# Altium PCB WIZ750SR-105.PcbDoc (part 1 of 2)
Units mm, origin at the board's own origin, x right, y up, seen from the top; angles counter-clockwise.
Board outline 62 x 40 mm, 4 copper layers (Top Layer, Signal Layer 1, Internal Plane 1, Bottom Layer), stack 0.844 mm thick; 87 components, 85 nets, 410 pads, 285 vias.
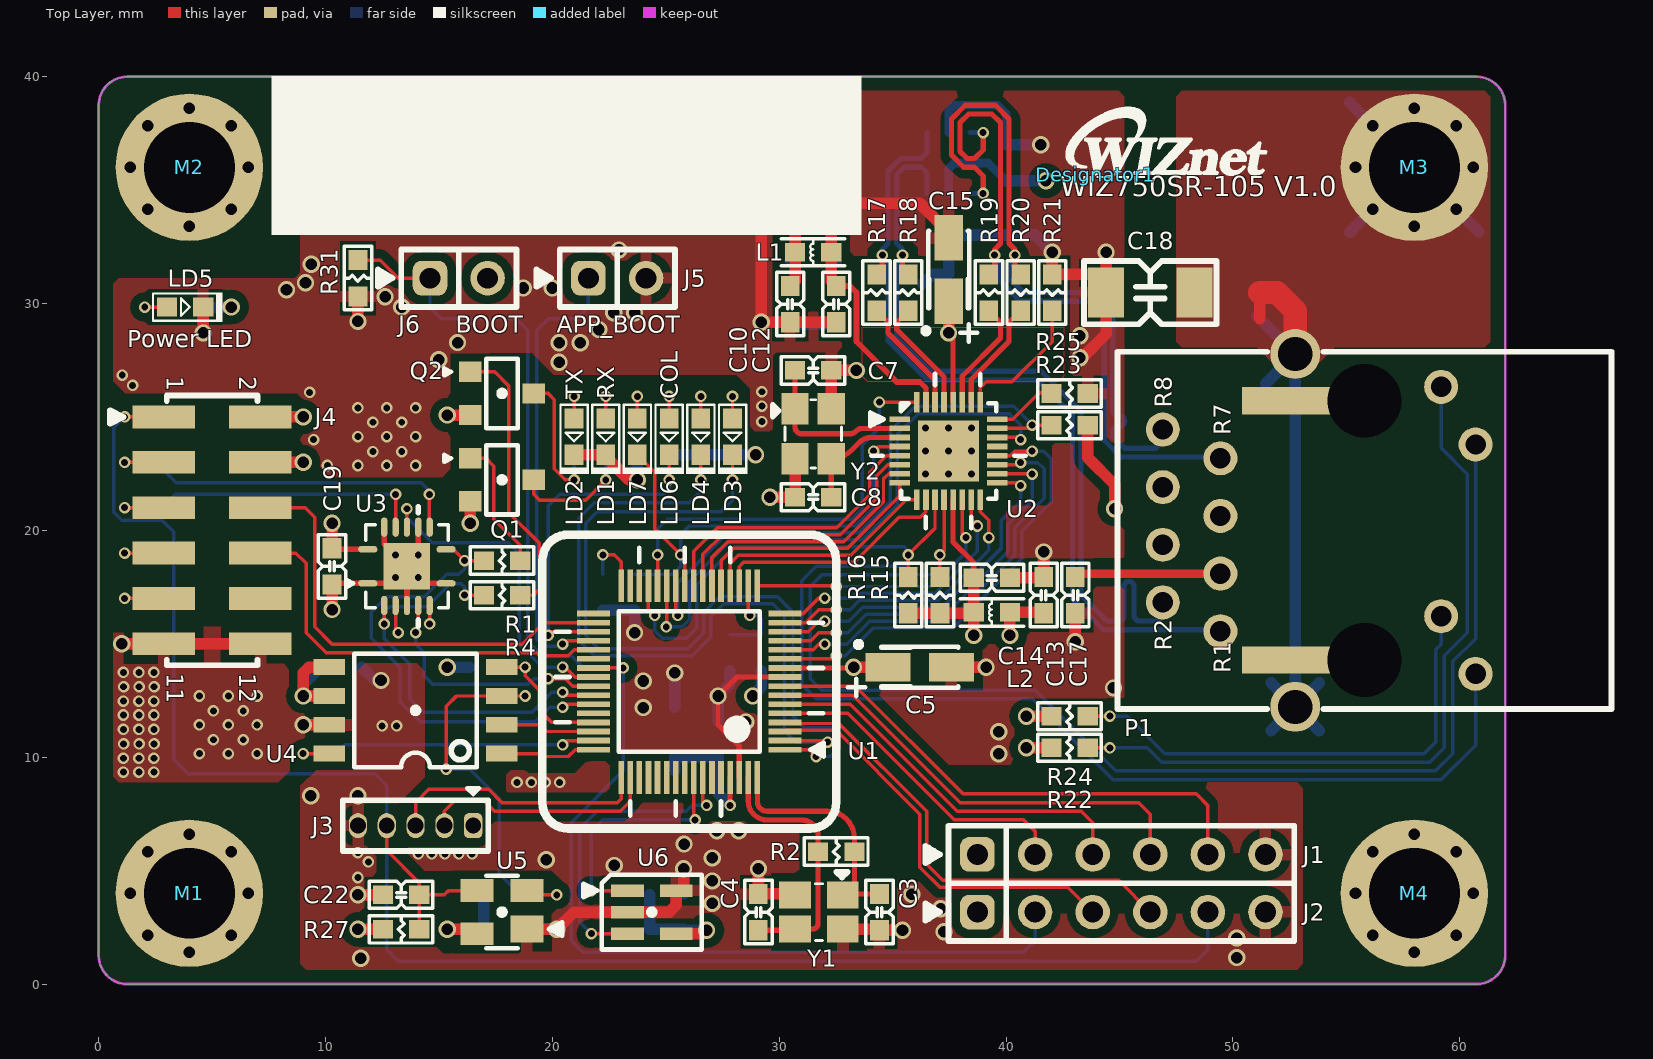
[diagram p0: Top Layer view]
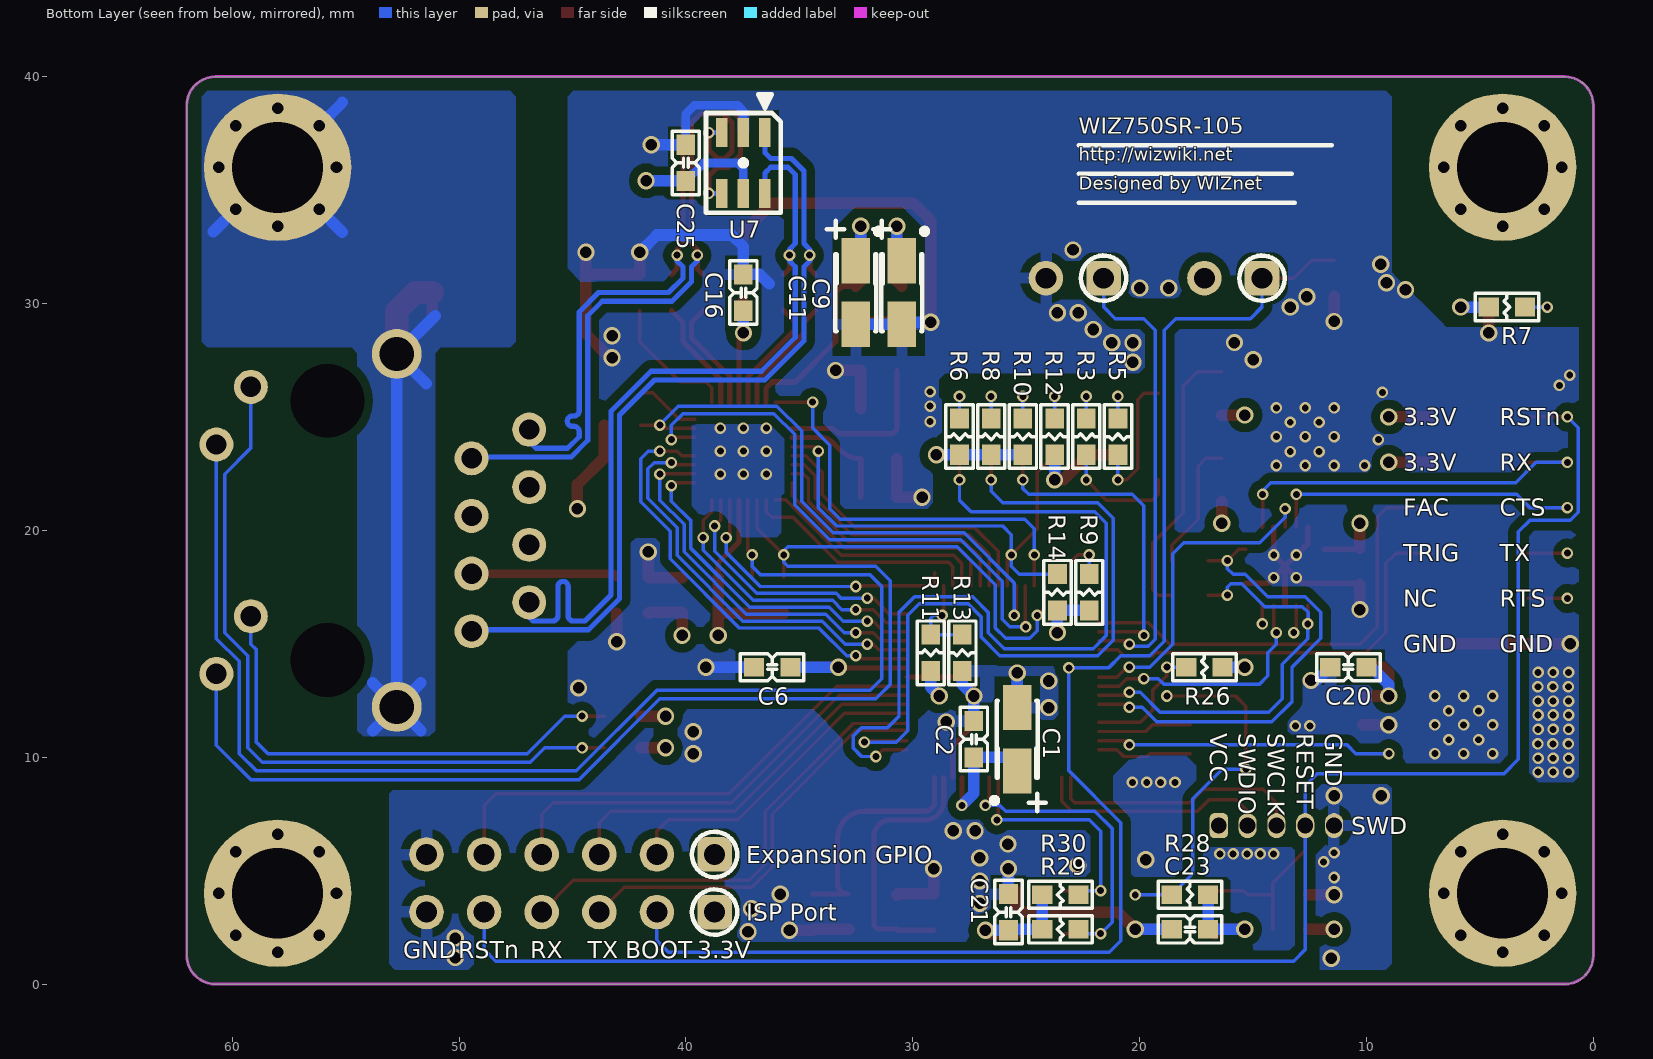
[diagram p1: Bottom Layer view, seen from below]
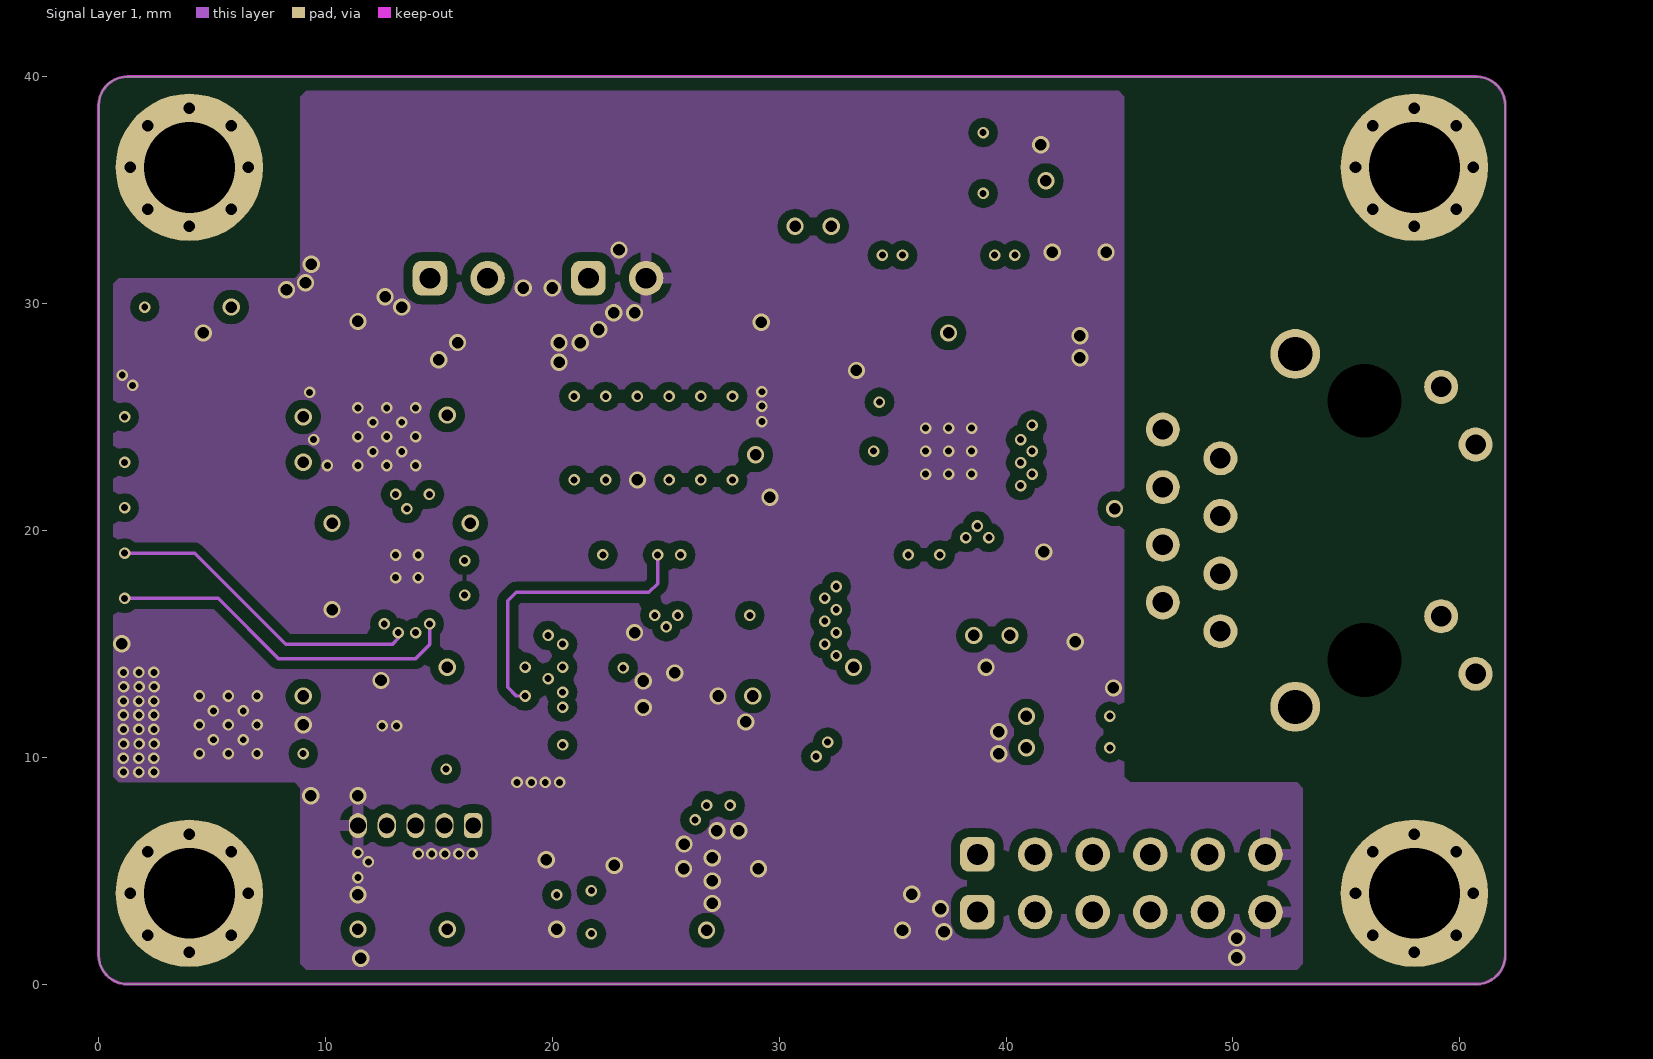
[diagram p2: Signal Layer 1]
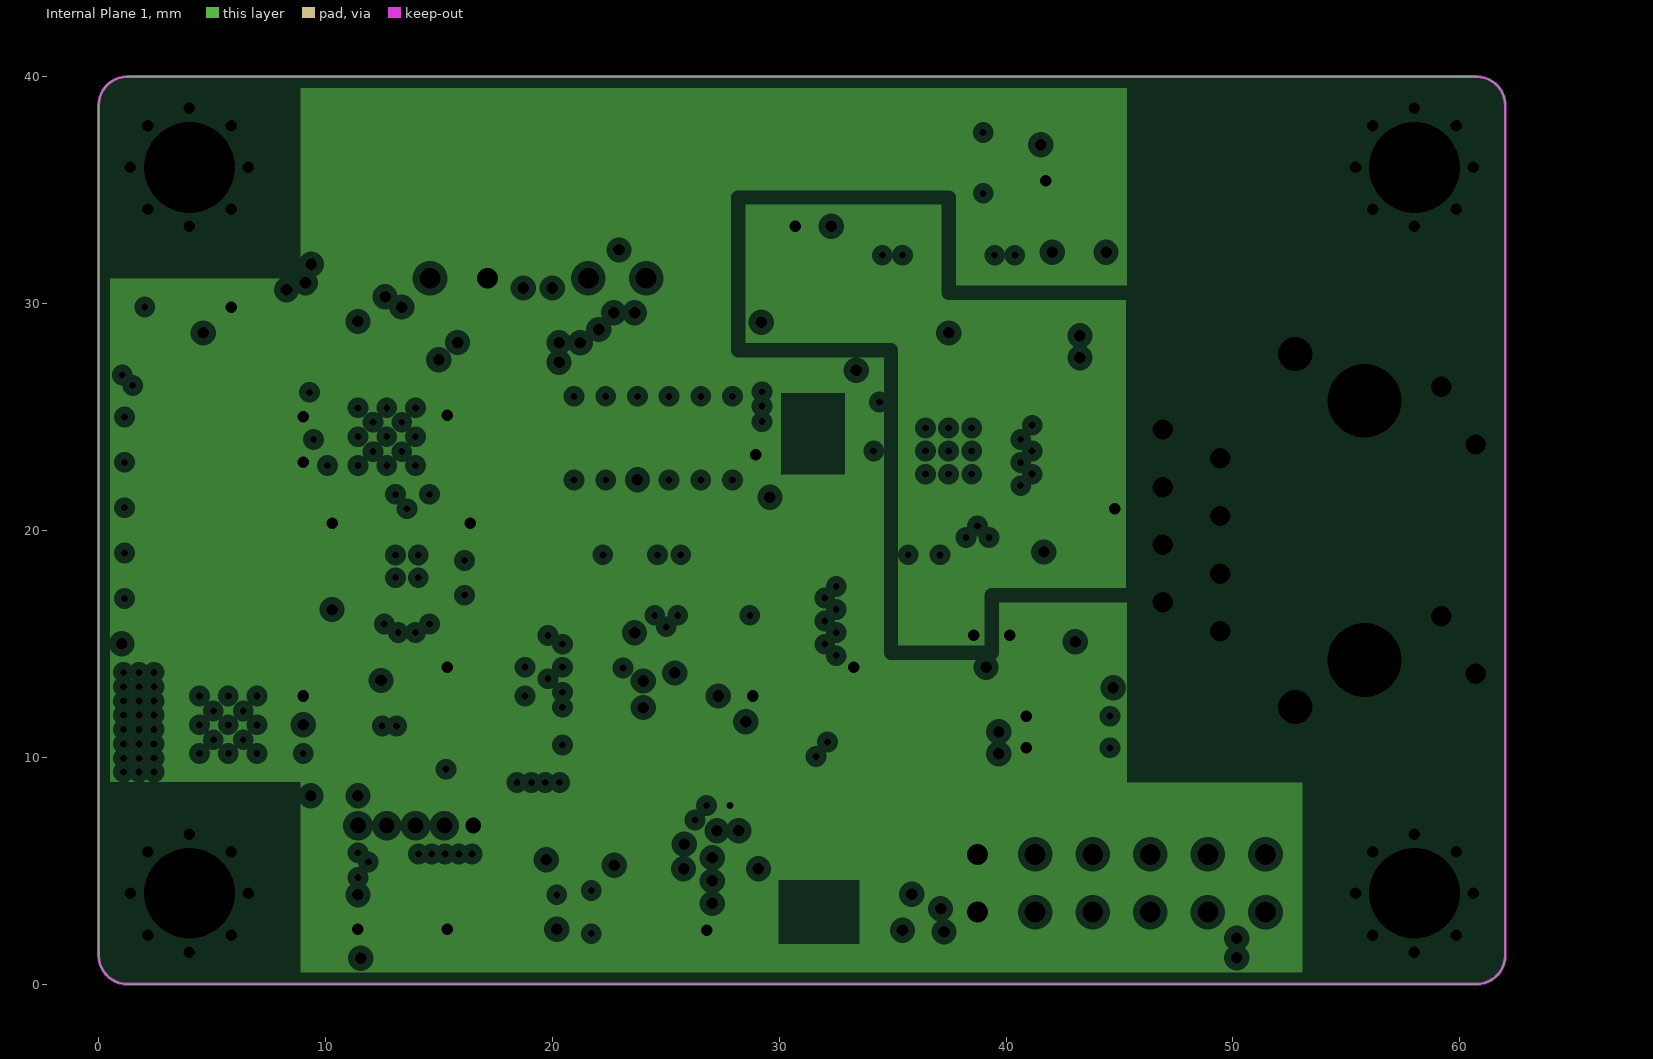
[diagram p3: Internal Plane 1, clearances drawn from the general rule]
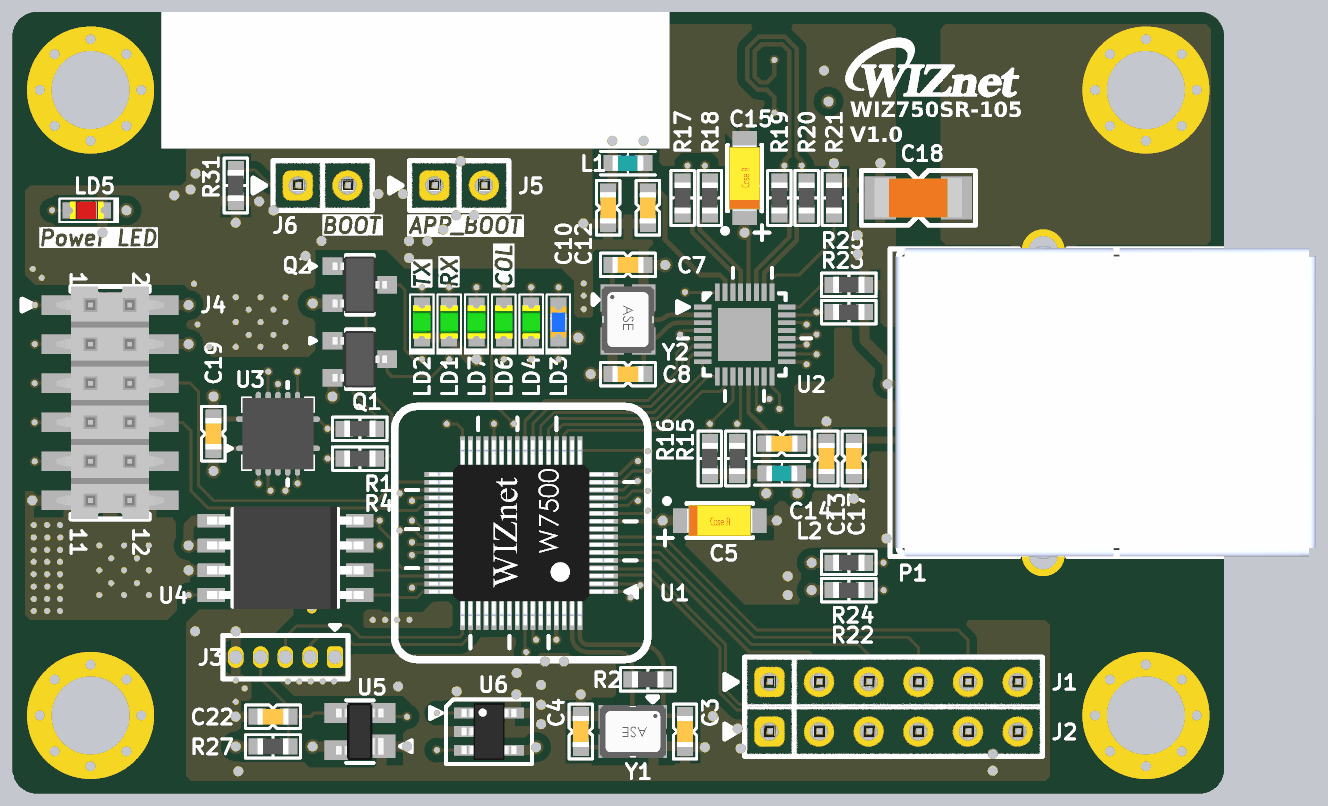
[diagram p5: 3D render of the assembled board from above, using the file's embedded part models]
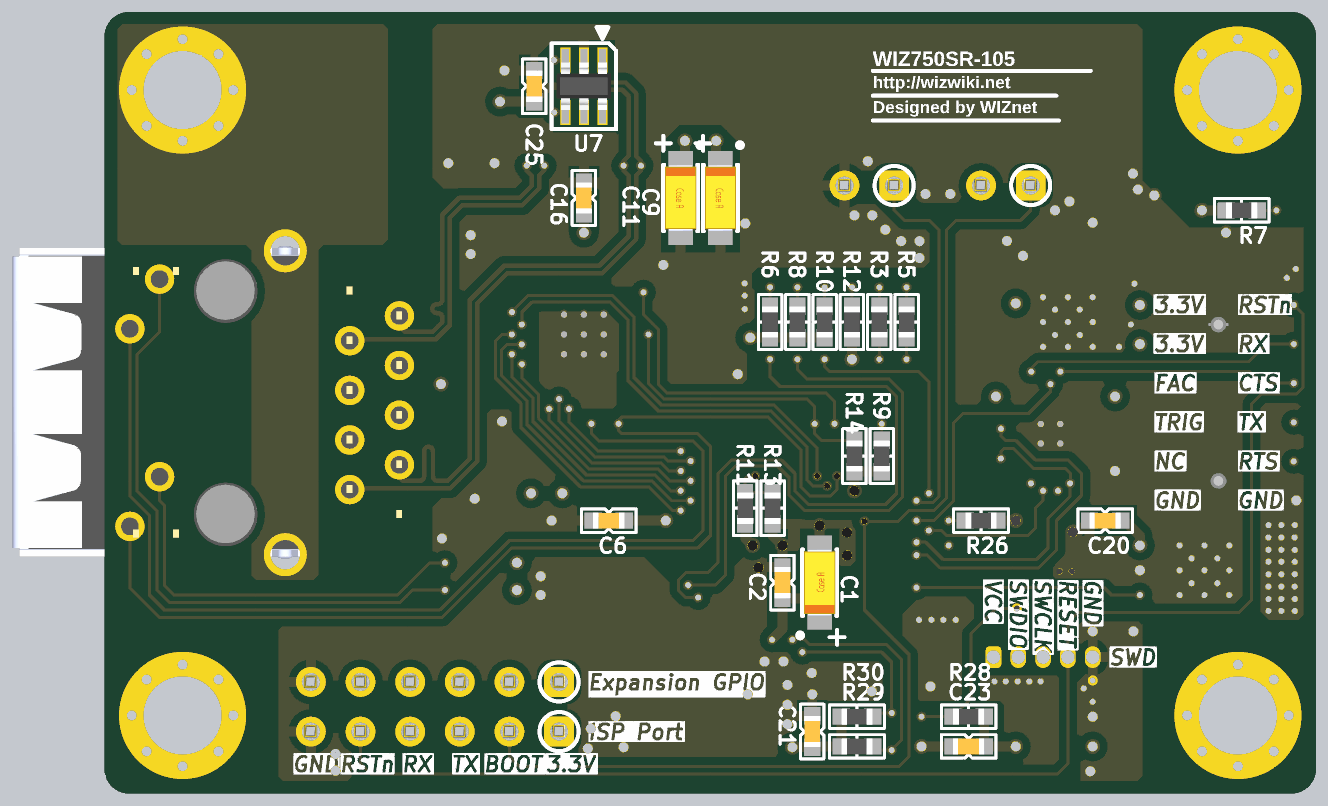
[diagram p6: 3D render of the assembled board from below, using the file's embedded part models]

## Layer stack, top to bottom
Top Solder: solder mask 0.0102, Solder Resist, Dk 3.5
Top Layer: signal copper 0.0356
Dielectric1: core 0.32, FR-4, Dk 4.8
Signal Layer 1: signal copper 0.036
Dielectric 6: prepreg 0.127, Dk 4.2
Internal Plane 1: plane copper 0.0356, net (Multiple Nets)
Dielectric5: core 0.254, FR-4, Dk 4.2
Bottom Layer: signal copper 0.0356
Bottom Solder: solder mask 0.0102, Solder Resist, Dk 3.5

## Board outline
0,1.27 0,38.73 cw(c1.27,38.73) 1.27,40 60.73,40 cw(c60.73,38.73) 62,38.73 62,1.27 cw(c60.73,1.27) 60.73,0 1.27,0 cw(c1.27,1.27)

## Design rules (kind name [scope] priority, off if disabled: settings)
Clearance [All] p1: gap=0.15 except(0.381: Arc-Poly Track-Poly SMDPad-Poly THPad-Poly Via-Poly Fill-Poly Poly-Poly Poly-Region)
DiffPairsRouting [All] p1: maxlimit=0.152 minlimit=0.152 mostfreqgap=0.152 toplayer_minwidth=0.152 toplayer_maxwidth=0.229 toplayer_prefwidth=0.229 midlayer1_minwidth=0.152 midlayer1_maxwidth=0.229 midlayer1_prefwidth=0.229 bottomlayer_minwidth=0.152 bottomlayer_maxwidth=0.229 bottomlayer_prefwidth=0.229 maxuncoupledlength=15.24
HoleSize [All] p1: absolutevalues=TRUE maxlimit=4.064 minlimit=0.025 maxpercent=80.000 minpercent=20.000
PlaneClearance [All] p1: clearance=0.305
PlaneConnect [All] p1: planeconnectstyle=Direct reliefexpansion=0.508 reliefentries=4 reliefconductorwidth=0.254 reliefairgap=0.254
PolygonConnect PolygonConnect_2 [IsPad vs IsNamedPolygon('Top Layer-GND') Or  IsNamedPolygon('Bottom Layer-GND')] p1: connectstyle=Relief reliefconductorwidth=0.508 reliefentries=4 polygonreliefangle="90 Angle" airgapwidth=0.381
PolygonConnect PolygonConnect_1 [IsVia] p2: connectstyle=Direct reliefconductorwidth=0.254 reliefentries=4 polygonreliefangle="90 Angle" airgapwidth=0.254
PolygonConnect [All] p3: connectstyle=Direct reliefconductorwidth=0.254 reliefentries=4 polygonreliefangle="90 Angle" airgapwidth=0.254
RoutingVias [All] p1: holewidth=0.305 width=0.508 viastyle="Through Hole" minholewidth=0.305 minwidth=0.508 maxholewidth=0.508 maxwidth=0.762
SolderMaskExpansion [All] p1: expansion=0
Width [All] p1: maxlimit=2.54 minlimit=0.102 preferedwidth=0.152
26 further rules are at their usual default settings.

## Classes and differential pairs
component class 1.WIZ750JR_W7500: LD2
differential pair MDI0_R: +MDI0_R_P -MDI0_R_N
differential pair MDI0_T: +MDI0_T_P -MDI0_T_N
differential pair MDI_R: +MDI_R_P -MDI_R_N
differential pair MDI_T: +MDI_T_P -MDI_T_N
differential pair NewDifferentialPair1: +U_TXD2 -U_RXD2
differential pair NewDifferentialPair2: +U_TXD0 -U_RXD0

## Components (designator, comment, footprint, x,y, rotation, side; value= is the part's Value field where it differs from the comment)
C1 "10uF/16V" "CAP-A Size" 25.4,10.795 r90 bottom
C2 "1uF" CAP-0603 27.305,10.795 r270 bottom
C3 "30pF" CAP-0603 34.417,3.175 r90 top
C4 "30pF" CAP-0603 29.083,3.175 r270 top
C5 "10uF/16V" "CAP-A Size" 36.195,13.97 r0 top
C6 "1uF" CAP-0603 36.195,13.97 r180 bottom
C7 "27pF" CAP-0603 31.496,27.051 r180 top
C8 "27pF" CAP-0603 31.496,21.463 r0 top
C9 "10uF/16V" "CAP-A Size" 30.48,30.48 r270 bottom
C10 "0.1uF" CAP-0603 30.48,29.972 r90 top
C11 "10uF/16V" "CAP-A Size" 32.512,30.48 r270 bottom
C12 "0.1uF" CAP-0603 32.512,29.972 r90 top
C13 "0.1uF" CAP-0603 41.656,17.145 r270 top
C14 "0.1uF" CAP-0603 39.37,17.907 r0 top
C15 "10uF/16V" "CAP-A Size" 37.465,31.496 r90 top
C16 "0.1uF" CAP-0603 37.465,30.48 r270 bottom
C17 "0.1uF" CAP-0603 43.053,17.145 r90 top
C18 "1nF/2kV" CAP-1808 46.355,30.48 r0 top
C19 "0.1uF" CAP-0603 10.287,18.415 r270 top
C20 "0.1uF(NM)" CAP-0603 10.795,13.97 r0 bottom
C21 "0.1uF(NM)" CAP-0603 25.781,3.175 r270 bottom
C22 "0.1uF" CAP-0603 13.335,3.937 r0 top
C23 "0.1uF" CAP-0603 17.78,2.413 r180 bottom
C25 "0.1uF" CAP-0603 40.005,36.195 r90 bottom
Designator1 "Comment" LOGO-WIZNET(SMALL) 43.942,35.687 r0 top locked
J1 "2.54mm 1x6 Pin Header DIP" IDC-1X6 38.735,5.715 r0 top
J2 "2.54mm 1x6 Pin Header DIP(NM)" IDC-1X6 38.735,3.175 r0 top
J3 "1.27mm_1x5_Pin_header_DIP(NM)" IDC-1X5(1.27MM) 16.51,6.985 r180 top
J4 "2.00mm 6x2 Pin Header SMD" MOLEX-SD-87759-12 5,20 r270 top locked
J5 "2.54mm 1x2 Pin Header DIP" IDC-1X2 21.59,31.115 r0 top
J6 "2.54mm 1x2 Pin Header DIP" IDC-1X2 14.605,31.115 r0 top
L1 "HH-1M1608-121JT" IND-0603 31.496,32.258 r180 top
L2 "HH-1M1608-121JT" IND-0603 39.37,16.383 r180 top
LD1 "GREEN-0603" LED-0603-GREEN 22.352,24.13 r270 top
LD2 "GREEN-0603" LED-0603-GREEN 20.955,24.13 r270 top
LD3 "BLUE-0603" LED-0603-BLUE 27.94,24.13 r270 top
LD4 "GREEN-0603" LED-0603-GREEN 26.543,24.13 r270 top
LD5 "RED-0603" LED-0603-RED 3.81,29.845 r0 top
LD6 "GREEN-0603" LED-0603-GREEN 25.146,24.13 r270 top
LD7 "GREEN-0603" LED-0603-GREEN 23.749,24.13 r270 top
M1 "Comment" HOLE-4/6.5 4,4 r0 top locked
M2 "Comment" HOLE-4/6.5 4,36 r0 top locked
M3 "Comment" HOLE-4/6.5 58,36 r0 top locked
M4 "Comment" HOLE-4/6.5 58,4 r0 top locked
P1 "BS-RB10005" RJ45-RB10005 55.795,20 r90 top locked
Q1 "Q-MMBT4403" SOT-23-3L 17.78,22.225 r270 top
Q2 "Q-MMBT4403" SOT-23-3L 17.78,26.035 r270 top
R1 "1K" RES-0603 17.78,18.669 r180 top
R2 "1M" RES-0603 32.512,5.842 r180 top
R3 "330R" RES-0603 22.352,24.13 r270 bottom
R4 "1K" RES-0603 17.78,17.145 r180 top
R5 "330R" RES-0603 20.955,24.13 r90 bottom
R6 "1K" RES-0603 27.94,24.13 r270 bottom
R7 "330R" RES-0603 3.81,29.845 r180 bottom
R8 "330R" RES-0603 26.543,24.13 r270 bottom
R9 "4.7K" RES-0603 22.225,17.272 r90 bottom
R10 "330R" RES-0603 25.146,24.13 r270 bottom
R11 "4.7K/NC" RES-0603 29.21,14.605 r270 bottom
R12 "330R" RES-0603 23.749,24.13 r270 bottom
R13 "4.7K" RES-0603 27.813,14.605 r90 bottom
R14 "5.1K" RES-0603 23.622,17.272 r90 bottom
R15 "5.1K" RES-0603 37.084,17.145 r90 top
R16 "5.1K" RES-0603 35.687,17.145 r90 top
R17 "3.3R" RES-0603 34.29,30.48 r270 top
R18 "3.3R" RES-0603 35.687,30.48 r270 top
R19 "3.3R" RES-0603 39.243,30.48 r270 top
R20 "3.3R" RES-0603 40.64,30.48 r270 top
R21 "6.19K / 1%" RES-0603 42.037,30.48 r270 top
R22 "330R" RES-0603 42.799,10.414 r0 top
R23 "5.1K" RES-0603 42.799,24.638 r0 top
R24 "330R" RES-0603 42.799,11.811 r0 top
R25 "5.1K" RES-0603 42.799,26.035 r180 top
R26 "4.7K(NM)" RES-0603 17.145,13.97 r180 bottom
R27 "4.7K" RES-0603 13.335,2.413 r180 top
R28 "4.7K" RES-0603 17.78,3.937 r180 bottom
R29 "4.7K(NM)" RES-0603 23.495,2.413 r0 bottom
R30 "4.7K(NM)" RES-0603 23.495,3.937 r0 bottom
R31 "4.7K" RES-0603 11.43,31.115 r270 top
U1 "W7500" W7500-LQFP64 26.035,13.335 r180 top locked
U2 "IP101GR/GRI" QFN32(0.4/4X4) 37.465,23.495 r0 top locked
U3 "SN74LVC125A" VQFN14(0.5/3.65X3.65) 13.589,18.415 r0 top locked
U4 "AT45DB161E-SHF-T" SO-08-EIAJ 13.97,12.065 r180 top
U5 "MIC811SUY" SOT-143 17.78,3.175 r90 top
U6 "24AA16T-I/OT" SOT-23-5L 24.384,3.175 r0 top locked
U7 "TPD4S009" SOT-23-6L 37.465,36.195 r270 bottom
Y1 "12MHz" OSC-TZ1067B 31.75,3.175 r180 top
Y2 "25MHz" OSC-82J0626 31.496,24.257 r270 top

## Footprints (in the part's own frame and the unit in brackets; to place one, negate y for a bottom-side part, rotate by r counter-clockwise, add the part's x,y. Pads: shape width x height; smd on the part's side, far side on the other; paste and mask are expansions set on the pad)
CAP-0603 [mm] "Ceramic CAP 0603(1608)"
  rect 0.89x0.82 smd: 1(-0.8,0) 2(0.8,0)
  silkscreen extent -1.4,-0.6 1.4,0.6, body extent -0.93,-0.41 0.93,0.41, height 0.81
CAP-1808 [mm] "Ceramic CAP 1808(4520)"
  rect 1.6x2.2 smd: 1(-1.95,0) 2(1.95,0)
  silkscreen extent -2.92,-1.4 2.92,1.4, body extent -2.25,-1.02 2.25,1.01, height 2
"CAP-A Size" [mm] "Tantal CAP A Size EIA/IECQ 3216"
  rect 2x1.25 smd: 1(-1.4,0) 2(1.4,0)
  silkscreen extent -3.17,-1.27 1.7,1.12, body extent -1.7,-0.8 1.7,0.8, height 1.75
HOLE-4/6.5 [mm]
  round 6.5 hole 4: 1(0,0)
IDC-1X2 [mil]
  rrect50% 60x60 hole 36: 1(0,0)
  round 60 hole 36: 2(100,0)
  silkscreen extent -90,-50 150,50, body extent -49,-49 151,51, height 336
IDC-1X5(1.27MM) [mm]
  rrect50% 0.8x1.1 hole 0.7: 1(0,0)
  oval 0.8x1.1 hole 0.7: 2(1.27,0) 3(2.54,0) 4(3.81,0) 5(5.08,0)
  silkscreen extent -0.66,-1.65 5.74,1.11
IDC-1X6 [mil] "6-Way 2.54 mm Male Header"
  rrect50% 60x60 hole 36: 1(0,0)
  round 60 hole 36: 2(100,0) 3(200,0) 4(300,0) 5(400,0) 6(500,0)
  silkscreen extent -90,-50 550,50, body extent -49,-49 551,51, height 336
IND-0603 [mm] "Inductor 0603(1608)"
  rect 0.89x0.82 smd: 1(-0.8,0) 2(0.8,0)
  Top Layer pour cut-out: -0.254,0.508 -0.254,-0.508 0.254,-0.508 0.254,0.508
  silkscreen extent -1.4,-0.6 1.4,0.6, body extent -0.8,-0.4 0.8,0.4, height 0.95
LED-0603-BLUE [mm] "LED-0603-GREEN"
  rect 0.89x0.82 smd: 1(-0.8,0) 2(0.8,0)
  silkscreen extent -1.41,-0.65 1.65,0.65, body extent -0.8,-0.4 0.8,0.4, height 0.6
LED-0603-GREEN [mm] "LED-0603-GREEN"
  rect 0.89x0.82 smd: 1(-0.8,0) 2(0.8,0)
  silkscreen extent -1.41,-0.65 1.65,0.65, body extent -0.85,-0.45 0.85,0.45, height 0.9
LED-0603-RED [mm] "LED-0603-RED"
  rect 0.89x0.82 smd: 1(-0.8,0) 2(0.8,0)
  silkscreen extent -1.41,-0.65 1.65,0.65, body extent -0.85,-0.45 0.85,0.45, height 0.9
LOGO-WIZNET(SMALL) [mm]
  silkscreen extent -1.27,0 7.52,2.93
MOLEX-SD-87759-12 [mm]
  rect 1x2.75 smd: 1(-5,-2.13) 2(-5,2.13) 3(-3,-2.13) 4(-3,2.13) 5(-1,-2.13) 6(-1,2.13) 7(1,-2.13) 8(1,2.13) 9(3,-2.13) 10(3,2.13) 11(5,-2.13) 12(5,2.13)
  silkscreen extent -5.95,-4.5 5.95,2, body extent -5.95,-2.75 5.95,2.75, height 6.55
OSC-82J0626 [mm]
  rect 1.4x1.2 smd: 1(-1.1,-0.8) 2(1.1,-0.8) 3(1.1,0.8) 4(-1.1,0.8)
  silkscreen extent -1.5,-1.78 1.5,1.25, body extent -1.7,-1.35 1.7,1.35, height 1.06
OSC-TZ1067B [mm]
  rect 1.4x1.2 smd: 1(-1.05,-0.75) 2(1.05,-0.75) 3(1.05,0.75) 4(-1.05,0.75)
  silkscreen extent -1.27,-1.78 0.15,1.25, body extent -1.7,-1.35 1.7,1.35, height 1.06
QFN32(0.4/4X4) [mm]
  rect 0.9x0.25 smd: 1(-2.15,1.4) 2(-2.15,1) 3(-2.15,0.6) 4(-2.15,0.2) 5(-2.15,-0.2) 6(-2.15,-0.6) 7(-2.15,-1) 8(-2.15,-1.4) 17(2.15,-1.4) 18(2.15,-1) 19(2.15,-0.6) 20(2.15,-0.2) 21(2.15,0.2) 22(2.15,0.6) 23(2.15,1) 24(2.15,1.4)
  rect 0.25x0.9 smd: 9(-1.4,-2.15) 10(-1,-2.15) 11(-0.6,-2.15) 12(-0.2,-2.15) 13(0.2,-2.15) 14(0.6,-2.15) 15(1,-2.15) 16(1.4,-2.15) 25(1.4,2.15) 26(1,2.15) 27(0.6,2.15) 28(0.2,2.15) 29(-0.2,2.15) 30(-0.6,2.15) 31(-1,2.15) 32(-1.4,2.15)
  rect 2.7x2.7 smd: 33(0,0)
  silkscreen extent -3.45,-3.4 3.4,3.4, body extent -2.1,-2.1 2.1,2.1, height 0.76
RES-0603 [mm] "RES-0603"
  rect 0.89x0.82 smd: 1(-0.8,0) 2(0.8,0)
  silkscreen extent -1.4,-0.6 1.4,0.6, body extent -0.82,-0.41 0.82,0.41, height 0.46
RJ45-RB10005 [mm]
  round 2.2 hole 1.5: 0(-7.775,3.05) 0(7.775,3.05)
  round 1.5 hole 0.9: L1(6.325,-3.38) L2(3.785,-4.9) L3(-3.785,-3.38) L4(-6.325,-4.9) R1(-4.445,6.35) R2(-3.175,8.89) R3(-1.905,6.35) R4(-0.635,8.89) R5(0.635,6.35) R6(1.905,8.89) R7(3.175,6.35) R8(4.445,8.89)
  round 3 hole 3.25 unplated paste+0 mask+0.102: ""(-5.715,0) ""(5.715,0)
  rect 1.2x4.7 smd: ""(-5.715,3.05) ""(5.715,3.05)
  silkscreen extent -7.88,-10.89 7.88,10.89, body extent -7.97,-10.9 8.03,10.6, height 12.67
SO-08-EIAJ [mm]
  rect 1.4x0.7 smd: 1(-3.8,1.905) 2(-3.8,0.635) 3(-3.8,-0.635) 4(-3.8,-1.905) 5(3.8,-1.905) 6(3.8,-0.635) 7(3.8,0.635) 8(3.8,1.905)
  silkscreen extent -2.7,-2.5 2.7,2.5, body extent -4,-2.62 4,2.63, height 2.58
SOT-23-3L [mm]
  rect 0.9x1 smd: 1(-0.95,-1.4) 2(0.95,-1.4) 3(0,1.4)
  silkscreen extent -1.53,-2.55 1.53,0.7, body extent -1.45,-1.4 1.45,1.4, height 1.28
SOT-23-5L [mm]
  rect 1.45x0.55 smd: 1(-1.075,0.95) 2(-1.075,0) 3(-1.075,-0.95) 4(1.075,-0.95) 5(1.075,0.95)
  silkscreen extent -3.01,-1.65 2.2,1.65, body extent -1.4,-1.45 1.4,1.45, height 1.45
SOT-23-6L [mm]
  rect 1.27x0.508 smd paste-0.07: 1(-1.34,0.95) 2(-1.34,0) 3(-1.34,-0.95) 4(1.34,-0.95) 5(1.34,0) 6(1.34,0.95)
  silkscreen extent -3.02,-1.65 2.2,1.65, body extent -1.21,-1.4 1.21,1.4, height 1.09
SOT-143 [mm]
  rect 1.2x1.44 smd: 1(-0.75,-1.1)
  rect 1x1.44 smd: 2(0.95,-1.1) 3(0.95,1.1) 4(-0.95,1.1)
  silkscreen extent -1.6,-2.65 1.6,0.7, body extent -1.46,-1.21 1.46,1.21, height 1
VQFN14(0.5/3.65X3.65) [mm]
  oval 0.85x0.28 smd: 1(-1.725,-0.75) 7(1.725,-0.75) 8(1.725,0.75) 14(-1.725,0.75)
  oval 0.28x0.85 smd: 2(-1,-1.725) 3(-0.5,-1.725) 4(0,-1.725) 5(0.5,-1.725) 6(1,-1.725) 9(1,1.725) 10(0.5,1.725) 11(0,1.725) 12(-0.5,1.725) 13(-1,1.725)
  rect 2.05x2.05 smd: 15(0,0)
  silkscreen extent -2.66,-2.63 1.83,2.63, body extent -1.82,-1.82 1.83,1.83, height 1
W7500-LQFP64 [mm] "WIZnet ARM Cortex-M0, LQFP64, Pitch 0.40mm"
  rect 1.45x0.25 smd: 1(-4.225,3) 2(-4.225,2.6) 3(-4.225,2.2) 4(-4.225,1.8) 5(-4.225,1.4) 6(-4.225,1) 7(-4.225,0.6) 8(-4.225,0.2) 9(-4.225,-0.2) 10(-4.225,-0.6) 11(-4.225,-1) 12(-4.225,-1.4) 13(-4.225,-1.8) 14(-4.225,-2.2) 15(-4.225,-2.6) 16(-4.225,-3) 33(4.225,-3) 34(4.225,-2.6) 35(4.225,-2.2) 36(4.225,-1.8) 37(4.225,-1.4) 38(4.225,-1) 39(4.225,-0.6) 40(4.225,-0.2) 41(4.225,0.2) 42(4.225,0.6) 43(4.225,1) 44(4.225,1.4) 45(4.225,1.8) 46(4.225,2.2) 47(4.225,2.6) 48(4.225,3)
  rect 0.25x1.45 smd: 17(-3,-4.225) 18(-2.6,-4.225) 19(-2.2,-4.225) 20(-1.8,-4.225) 21(-1.4,-4.225) 22(-1,-4.225) 23(-0.6,-4.225) 24(-0.2,-4.225) 25(0.2,-4.225) 26(0.6,-4.225) 27(1,-4.225) 28(1.4,-4.225) 29(1.8,-4.225) 30(2.2,-4.225) 31(2.6,-4.225) 32(3,-4.225) 49(3,4.225) 50(2.6,4.225) 51(2.2,4.225) 52(1.8,4.225) 53(1.4,4.225) 54(1,4.225) 55(0.6,4.225) 56(0.2,4.225) 57(-0.2,4.225) 58(-0.6,4.225) 59(-1,4.225) 60(-1.4,4.225) 61(-1.8,4.225) 62(-2.2,4.225) 63(-2.6,4.225) 64(-3,4.225)
  silkscreen extent -6.48,-6.48 6.48,6.48, body extent -4.73,-4.74 4.73,4.72, height 1

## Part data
C1 C5 C9 C11 C15: library part "CAP-A Size", "Tantla CAP A Size EIA/IECQ 3216"
C2 C3 C4 C6 C7 C8 C10 C12 C13 C14 C16 C17 C19 C20 C21 C22 C23: library part CAP-0402, "Ceramic CAP 0402(1005)"
C18: library part CAP-1808, "Ceramic CAP 1808(4520)"
C25: library part CAP-0603, "Ceramic CAP 0603(1608)"
J2: library part "Header 6", "Header, 6-Pin"
J3: library part 1.27mm_1x5_Pin_header_DIP, "1.27mm_1x5_Pin_header_DIP"
J4: library part "Header 6X2", "Header, 6-Pin, Dual row"
J5 J6: library part "Header 1x2", "pin header 2.54mm 1x2"
L1 L2: library part IND-0603, "Inductor 0603(1608)"
LD1 LD2 LD3 LD4 LD5 LD6 LD7: library part LED-0603, "LED-0603"
P1: library part RB1-125BAG1A, "10/100 BASE-TX MAGJACK"
Q1 Q2: "PNP General-Purpose Amplifier"
R1 R2 R3 R4 R5 R6 R7 R8 R9 R10 R11 R13 R14 R17 R18 R19 R20 R21 R22 R23 R24 R25 R26 R27 R28 R29 R30 R31: library part RES-0402, "RES-0402"
R12: library part RES-0603, "RES-0603"
R15 R16: library part RES-0603, "RES-0402"
U1: "WIZnet ARM Cortex-M0"
U3: "Quadruple Bus Buffer Gate With 3-State Outputs"
U4: "16-Mbit DataFlash, 2.3V or 2.5V Minimum SPI Serial Flash Memory"
U5: "Microprocessor Reset Circuits"
U6: library part 24AAxxT-i-OT, "SOT-23"
U7: library part tpd4s009, "6-PIN SOT DBVor DCK Package"
Y1: library part OSC-TZ1067B-12MHz, "X-tal 12MHz,3.2x2.5 SMD, CL=20pF"
Y2: library part OSC-82J0626-25MHz, "X-tal 25MHz,3.2x2.5 SMD, CL=18pF"

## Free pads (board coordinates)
  round 0.457 on Mech3: 1(10.642,16.499) 1(10.642,17.287) 1(10.642,18.1) 1(10.642,18.887) 1(10.642,20.513) 1(10.642,21.3) 1(10.642,22.087) 1(10.642,22.9) 1(10.642,23.713) 1(10.642,24.5) 1(12.064,16.499) 1(12.064,17.287) 1(12.064,18.1) 1(12.064,18.887) 1(12.064,20.513) 1(12.064,21.3) 1(12.064,22.087) 1(12.064,22.9) 1(12.064,23.713) 1(12.064,24.5) 1(13.499,25.936) 1(13.499,27.358) 1(14.287,13.642) 1(14.287,15.064) 1(14.287,25.936) 1(14.287,27.358) 1(15.1,13.642) 1(15.1,15.064) 1(15.1,25.936) 1(15.1,27.358) 1(15.887,13.642) 1(15.887,15.064) 1(16.7,13.642) 1(16.7,15.064) 1(16.7,25.936) 1(16.7,27.358) 1(17.487,13.642) 1(17.487,15.064) 1(17.487,25.936) 1(17.487,27.358) 1(18.3,13.642) 1(18.3,15.064) 1(18.3,25.936) 1(18.3,27.358) 1(19.087,13.642) 1(19.087,15.064) 1(19.087,25.936) 1(19.087,27.358) 1(19.9,13.642) 1(19.9,15.064) 1(19.9,25.936) 1(19.9,27.358) 1(20.688,25.936) 1(20.688,27.358) 1(21.5,13.642) 1(21.5,15.064) 1(21.5,25.936) 1(21.5,27.358) 1(22.936,16.499) 1(22.936,17.287) 1(22.936,18.1) 1(22.936,18.887) 1(22.936,19.7) 1(22.936,20.513) 1(22.936,21.3) 1(22.936,22.087) 1(22.936,23.713) 1(22.936,24.5) 1(24.358,16.499) 1(24.358,17.287) 1(24.358,18.1) 1(24.358,18.887) 1(24.358,19.7) 1(24.358,20.513) 1(24.358,21.3) 1(24.358,22.087) 1(24.358,23.713) 1(24.358,24.5)

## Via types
v1: diameter 0.508, hole 0.305, Top Layer to Bottom Layer, tented both sides, 164 vias
v2: diameter 0.762, hole 0.508, Top Layer to Bottom Layer, tented both sides, 119 vias
v3: diameter 0.508, hole 0.305, Top Layer to Bottom Layer, 1 vias
v4: diameter 0.508, hole 0.305, Top Layer to Bottom Layer, tented top, 1 vias

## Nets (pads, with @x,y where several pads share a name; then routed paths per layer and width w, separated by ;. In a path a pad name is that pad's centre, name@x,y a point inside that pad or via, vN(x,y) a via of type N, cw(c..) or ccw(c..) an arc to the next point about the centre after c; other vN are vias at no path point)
APP_BOOT: J5.1 U1.36 | length 20.3
  Top Layer w0.152: v1(20.447,14.986) 20.596,15.135 U1.36@21.81,15.135
  Bottom Layer w0.152: v1(20.447,14.986) 20.348,14.887 19.613,14.887 19.304,15.196 19.304,28.829 19.812,29.337 21.082,29.337 21.59,29.845 J5.1@21.59,31.115
BOOT: J2.2 J6.1 R31.1 U1.39 | length 64.3
  Top Layer w0.152: R31.1@11.43,31.915 12.408,31.915 13.208,31.115 J6.1@14.605,31.115 ; U1.39@21.81,13.935 v1(23.114,13.935)
  Bottom Layer w0.152: J6.1@14.605,31.115 14.605,29.845 15.113,29.337 18.415,29.337 18.923,28.829 18.923,15.113 19.558,14.478 20.828,14.478 21.371,13.935 v1(23.114,13.935) 23.114,9.398 20.828,7.112 20.828,1.905 21.336,1.397 40.767,1.397 41.275,1.905 J2.2@41.275,3.175
CH_GND: C18.2 M3.1 P1.0 | length 50.5
  Top Layer w0.508: 51.181,29.339 51.181,30.48 ; v2(56.162,34.162) M3.1@58,36 ; v2(56.162,37.838) M3.1@58,36 ; v2(59.838,34.162) M3.1@58,36
  Top Layer w1.016: 51.181,30.48 51.943,30.48 52.745,29.678 P1.0@52.745,27.775
  Bottom Layer w0.508: 51.054,29.466 P1.0@52.745,27.775 ; 51.435,26.465 P1.0@52.745,27.775 ; 51.689,11.176 P1.0@52.705,12.192 ; 51.693,13.277 P1.0@52.745,12.225 ; 53.797,11.173 P1.0@52.745,12.225 ; 53.797,13.277 P1.0@52.745,12.225 ; 55.138,38.862 v2(56.162,37.838) M3.1@58,36 ; 55.147,33.147 v2(56.162,34.162) M3.1@58,36 ; 60.833,33.167 v2(59.838,34.162) M3.1@58,36 ; P1.0@52.745,12.225 P1.0@52.745,27.775
  other v2: 58,33.4 55.4,36 60.6,36 59.838,37.838 58,38.6
DUP: R11.1 R13.2 U1.18 | length 4
  Top Layer w0.152: U1.18@28.635,17.56 28.635,16.323 v1(28.702,16.256)
  Bottom Layer w0.152: R13.2@27.813,15.405 R11.1@29.21,15.405 29.21,16.129 29.083,16.256 v1(28.702,16.256)
EX_RESETN: C22.2 J2.5 J3.4 J4.1 R27.1 U5.3 | length 82.3
  Top Layer w0.152: v1(1.143,25) J4.1@2.87,25 ; J3.4@12.7,6.985 12.7,5.893 14.135,4.458 C22.2@14.135,3.937 ; R27.1@14.135,2.413 C22.2@14.135,3.937 ; U5.3@16.68,4.125 15.428,4.125 15.24,3.937 C22.2@14.135,3.937
  Bottom Layer w0.152: v1(1.143,25) 0.663,24.52 0.663,20.8 1.016,20.447 2.794,20.447 3.302,19.939 3.302,9.906 3.937,9.271 12.167,9.271 12.7,8.738 J3.4@12.7,6.985 12.7,1.524 13.208,1.016 48.387,1.016 48.895,1.524 J2.5@48.895,3.175
EXPANSION_GPIO_A: J1.5 U1.8 | length 23
  Top Layer w0.152: U1.8@30.26,13.135 33.347,13.135 38.1,8.382 48.387,8.382 48.895,7.874 J1.5@48.895,5.715
EXPANSION_GPIO_B: J1.4 U1.7 | length 20
  Top Layer w0.152: U1.7@30.26,12.735 33.239,12.735 37.973,8.001 45.847,8.001 46.355,7.493 J1.4@46.355,5.715
EXPANSION_GPIO_C: J1.3 U1.6 | length 17.1
  Top Layer w0.152: U1.6@30.26,12.335 33.131,12.335 37.846,7.62 43.307,7.62 43.815,7.112 J1.3@43.815,5.715
EXPANSION_GPIO_D: J1.2 U1.5 | length 14.2
  Top Layer w0.152: U1.5@30.26,11.935 33.023,11.935 37.719,7.239 40.767,7.239 41.275,6.731 J1.2@41.275,5.715
FACTORY_RESET: J4.6 U1.34 | length 20.4
  Top Layer w0.152: J4.6@7.13,21 9.099,21 9.525,20.574 9.525,15.748 10.287,14.986 18.669,14.986 19.618,15.935 U1.34@21.81,15.935
GND: C1.2 C2.1 C3.1 C4.1 C5.2 C6.1 C7.1 C8.1 C9.2 C10.1 C11.2 C12.1 C13.1 C14.2 C15.2 C16.1 C17.1 C18.1 C19.2 C20.2 C21.1 C22.1 C23.1 C25.2 J1.6 J2.6 J3.5 J4.11 J4.12 J5.2 LD1.2 LD2.2 LD5.2 R9.1 R12.2 R13.1 R14.1 R21.1 R25.1 R31.2 U1.9 U1.62 U2.33 U3.1 U3.4 U3.7 U3.10 U3.13 U3.15 U4.7 U5.1 U6.2 U6.5 U7.2 Y1.2 Y1.4 Y2.2 Y2.4 | length 115.6
  Top Layer w0.229: U1.62@28.235,9.11 28.235,10.5 27.305,11.43 v2(27.305,12.7) 28.14,13.535 U1.9@30.26,13.535
  Top Layer w0.254: C19.2@10.287,17.615 C19.2@10.337,17.665 ; C19.2@10.464,17.665 U3.1@11.864,17.665 12.839,17.665 v1(13.089,17.915) U3.15@13.589,18.415 ; U3.13@12.589,20.14 12.589,19.415 v1(13.089,18.915) U3.15@13.589,18.415 ; U3.4@13.589,16.69 U3.15@13.589,18.415 ; U3.10@14.089,20.14 v1(14.089,18.915) U3.15@13.589,18.415 ; U3.7@15.314,17.665 14.339,17.665 v1(14.089,17.915) U3.15@13.589,18.415
  Top Layer w0.508: v2(1.016,15) J4.11@2.87,15 J4.12@7.13,15 ; v2(4.61,28.702) LD5.2@4.61,29.845 ; v2(9.017,11.43) U4.7@10.17,11.43 ; v2(10.287,16.51) C19.2@10.287,17.615 ; v2(11.43,3.937) C22.1@12.535,3.937 ; v2(11.43,29.21) R31.2@11.43,30.315 ; U5.1@18.88,2.425 18.892,2.413 v2(20.193,2.413) 20.955,3.175 U6.2@23.309,3.175 25.146,3.175 25.459,3.488 U6.5@25.459,4.125 25.781,4.125 v2(25.781,5.08) ; LD2.2@20.955,23.33 LD1.2@22.352,23.33 22.352,23.241 23.368,22.225 v2(23.749,22.225) ; v2(29.083,5.08) C4.1@29.083,3.975 30.65,3.975 Y1.2@30.7,3.925 ; v2(29.591,21.463) C8.1@30.696,21.463 Y2.2@30.696,23.157 ; Y2.4@32.296,25.357 C7.1@32.296,27.051 v2(33.401,27.051) ; C12.1@32.512,29.172 C10.1@30.48,29.172 v2(29.21,29.172) 29.21,33.655 29.972,34.417 36.195,34.417 37.465,33.147 C15.2@37.465,32.896 ; Y1.4@32.8,2.425 C3.1@34.367,2.425 ; C3.1@34.417,2.375 v2(35.433,2.375) ; C5.2@37.595,13.97 v2(39.116,13.97) ; C14.2@40.17,17.907 41.618,17.907 C13.1@41.656,17.945 v2(41.656,19.05) ; v2(42.037,32.258) R21.1@42.037,31.28 44.367,31.28 C18.1@44.405,31.242 ; v2(43.053,15.088) C17.1@43.053,16.345 ; v2(43.256,27.61) 43.307,27.61 43.332,27.584 44.405,28.657 C18.1@44.405,30.48 C18.1@44.405,31.242 ; v2(44.405,32.258) C18.1@44.405,31.242
  Bottom Layer w0.381: U7.2@37.465,37.535 37.465,38.481 37.719,38.735 39.624,38.735 40.005,38.354 C25.2@40.005,36.995
  Bottom Layer w0.508: C20.2@11.595,13.97 12.179,13.386 v2(12.446,13.386) ; C23.1@18.58,2.413 v2(20.193,2.413) ; R9.1@22.225,16.472 R14.1@23.622,16.472 v2(23.622,15.494) ; v2(23.749,22.225) R12.2@23.749,23.33 ; C1.2@25.4,12.195 v2(25.4,13.716) ; C21.1@25.781,3.975 v2(25.781,5.08) ; C2.1@27.305,11.595 v2(27.305,12.7) 27.813,13.208 R13.1@27.813,13.805 ; v2(29.21,29.172) 30.388,29.172 C9.2@30.48,29.08 C11.2@32.512,29.08 ; 36.322,30.861 36.741,31.28 C16.1@37.465,31.28 37.465,32.512 37.973,33.02 41.275,33.02 v2(42.037,32.258) ; C6.1@36.995,13.97 v2(39.116,13.97) ; C25.2@40.005,36.995 v2(41.529,36.995)
  other v1: 11.43,4.699 11.887,5.385 14.097,5.74 14.681,5.74 15.265,5.74 15.875,5.74 16.459,5.74 18.44,8.89 19.075,8.89 19.685,8.89 20.32,8.89 1.092,9.347 1.778,9.347 2.438,9.347 1.092,9.957 1.778,9.957 2.438,9.957 4.445,10.16 5.715,10.16 6.985,10.16 1.099,10.592 1.785,10.592 2.445,10.592 5.055,10.77 6.375,10.77 1.092,11.227 1.778,11.227 2.438,11.227 12.497,11.379 13.132,11.379 4.445,11.43 5.715,11.43 6.985,11.43 1.092,11.862 1.778,11.862 2.438,11.862 5.055,12.04 6.375,12.04 1.092,12.471 1.778,12.471 2.438,12.471 4.445,12.7 5.715,12.7 6.985,12.7 1.099,13.107 1.785,13.107 2.445,13.107 1.092,13.741 1.778,13.741 2.438,13.741 36.449,22.479 37.465,22.479 38.481,22.479 10.084,22.86 11.43,22.86 12.7,22.86 13.97,22.86 12.09,23.47 13.36,23.47 36.449,23.495 37.465,23.495 38.481,23.495 9.474,24.003 11.43,24.13 12.7,24.13 13.97,24.13 36.449,24.511 37.465,24.511 38.481,24.511 12.09,24.765 13.36,24.765 29.235,24.79 11.43,25.4 12.7,25.4 13.97,25.4 29.235,25.476 9.296,26.086 29.235,26.111 1.499,26.391 1.041,26.848
  other v2: 11.557,1.143 50.165,1.168 50.17,2.028 37.262,2.311 37.109,3.327 27.051,3.556 35.839,3.962 27.051,4.547 22.733,5.232 19.736,5.486 27.051,5.563 25.806,6.172 27.254,6.756 28.219,6.756 9.347,8.306 11.43,8.306 39.675,10.16 39.675,11.125 28.524,11.557 24.003,12.192 44.729,13.056 24.003,13.36 20.295,27.407 14.997,27.515 20.295,28.27 21.234,28.27 15.82,28.28 43.256,28.575 22.047,28.854 22.708,29.591 23.622,29.591 13.36,29.845 12.624,30.302 8.28,30.607 18.72,30.683 19.99,30.683 9.119,30.912 9.373,31.725 22.936,32.36
  other v4: 11.43,5.791
HW_TRIG: J4.8 U1.37 | length 18.4
  Top Layer w0.152: J4.8@7.13,19 8.686,19 9.144,18.542 9.144,15.494 10.033,14.605 19.304,14.605 19.431,14.478 20.701,14.478 20.958,14.735 U1.37@21.81,14.735
IN_CTS: J4.5 U3.12 | length 15.4
  Top Layer w0.152: v1(1.143,21) J4.5@2.87,21 ; U3.12@13.089,20.14 v1(13.089,21.59)
  Bottom Layer w0.152: v1(1.143,21) 2.794,21 3.384,21.59 v1(13.089,21.59)
IN_RXD: J4.3 U3.9 | length 17.3
  Top Layer w0.152: v1(1.143,23) J4.3@2.87,23 ; v1(14.58,21.59) 14.58,20.149 U3.9@14.589,20.14
  Bottom Layer w0.152: v1(1.143,23) 2.527,23 3.429,22.098 14.224,22.098 14.589,21.733 14.58,21.724 v1(14.58,21.59)
IP_3.3A: C11.1 C12.2 L1.1 U2.31 | length 11.8
  Top Layer w0.229: 36.195,26.543 36.465,26.273 U2.31@36.465,25.645
  Top Layer w0.254: C12.2@32.512,30.772 33.109,30.772 33.401,30.48 33.401,28.321 35.179,26.543 36.195,26.543
  Top Layer w0.508: v2@32.296,33.147 L1.1@32.296,32.258 32.296,30.988 C12.2@32.512,30.772
  Bottom Layer w0.508: v2(32.296,33.401) 32.296,32.096 C11.1@32.512,31.88
IP_3.3V: C9.1 C10.2 C14.1 L1.2 L2.2 R15.1 R16.1 R23.2 U2.13 | length 17.5
  Top Layer w0.229: U2.13@37.665,21.345 37.665,19.485 38.57,18.58 C14.1@38.57,17.907
  Top Layer w0.508: C10.2@30.48,30.772 30.696,30.988 L1.2@30.696,32.258 v2@30.696,33.147 ; R16.1@35.687,16.345 R15.1@37.084,16.345 38.532,16.345 L2.2@38.57,16.383 ; v2(38.57,15.367) L2.2@38.57,16.383 ; C14.1@38.57,17.907 L2.2@38.57,16.383 ; R23.2@43.599,24.638 43.599,23.203 44.78,22.022 v2(44.78,20.955)
  Bottom Layer w0.508: C9.1@30.48,31.88 30.696,32.096 v2(30.696,33.401)
MDI0_R_N: R20.2 U2.26 | length 4.9
  Top Layer w0.229: U2.26@38.465,25.645 38.465,26.654 40.132,28.321 40.132,29.172 R20.2@40.64,29.68
MDI0_R_P: R19.2 U2.27 | length 4.9
  Top Layer w0.229: U2.27@38.065,25.645 38.065,26.793 39.751,28.479 39.751,29.172 R19.2@39.243,29.68
MDI0_T_N: R18.2 U2.29 | length 5.1
  Top Layer w0.229: R18.2@35.687,29.68 35.179,29.172 35.179,28.86 37.265,26.774 U2.29@37.265,25.645
MDI0_T_P: R17.2 U2.30 | length 5.1
  Top Layer w0.229: R17.2@34.29,29.68 34.798,29.172 34.798,28.702 36.865,26.635 U2.30@36.865,25.645
MDI_R_N: P1.R8 R20.1 U7.4 | length 30.3
  Top Layer w0.229: v1(38.989,34.855) 38.989,35.623 38.608,36.005 38.133,36.005 37.592,36.545 37.592,38.131 38.196,38.735 39.528,38.735 40.132,38.131 40.132,32.639 40.386,32.385 v1(40.386,32.131) 40.386,31.534 R20.1@40.64,31.28
  Bottom Layer w0.229: U7.4@38.415,34.855 v1(38.989,34.855) ; v1(40.386,32.131) 40.386,31.877 40.132,31.623 40.132,31.115 40.767,30.48 43.846,30.48 44.704,29.622 44.704,25.273 ccw(c44.933,25.273) 44.933,25.044 44.999,25.044 cw(c44.999,24.816) 45.228,24.816 cw(c44.999,24.816) 44.999,24.587 44.933,24.587 ccw(c44.933,24.359) 44.704,24.359 44.704,24.257 44.704,24.13 45.212,23.622 46.609,23.622 46.905,23.918 P1.R8@46.905,24.445
MDI_R_P: P1.R7 R19.1 U7.3 | length 30.3
  Top Layer w0.229: v1(38.989,37.535) 38.989,36.767 38.608,36.386 38.291,36.386 37.973,36.703 37.973,37.973 38.354,38.354 39.37,38.354 39.751,37.973 39.751,32.639 39.497,32.385 v1(39.497,32.131) 39.497,31.534 R19.1@39.243,31.28
  Bottom Layer w0.229: U7.3@38.415,37.535 v1(38.989,37.535) ; v1(39.497,32.131) 39.497,31.877 39.751,31.623 39.751,30.957 40.609,30.099 43.688,30.099 44.323,29.464 44.323,23.972 45.054,23.241 49.379,23.241 P1.R7@49.445,23.175
MDI_T_N: P1.R2 R18.1 U7.6 | length 36.3
  Top Layer w0.229: v1(35.433,32.131) 35.433,31.534 R18.1@35.687,31.28
  Bottom Layer w0.229: U7.6@36.515,34.855 36.515,35.748 36.258,36.005 35.496,36.005 35.179,35.687 35.179,32.639 35.433,32.385 v1(35.433,32.131) 35.433,31.877 35.179,31.623 35.179,28.516 36.679,27.016 41.539,27.016 43.307,25.248 43.307,17.145 44.45,16.002 44.958,16.002 ccw(c44.958,16.231) 45.187,16.231 45.187,17.523 cw(c45.415,17.523) 45.415,17.751 cw(c45.415,17.523) 45.644,17.523 45.644,16.231 ccw(c45.872,16.231) 45.872,16.002 46.228,16.002 46.736,16.002 46.905,16.171 P1.R2@46.905,16.825
MDI_T_P: P1.R1 R17.1 U7.1 | length 36.3
  Top Layer w0.229: R17.1@34.29,31.28 34.544,31.534 v1(34.544,32.131)
  Bottom Layer w0.229: U7.1@36.515,37.535 36.515,36.642 36.258,36.386 35.339,36.386 34.798,35.845 34.798,32.639 34.544,32.385 v1(34.544,32.131) 34.544,31.877 34.798,31.623 34.798,28.358 36.522,26.635 41.381,26.635 42.926,25.09 42.926,16.987 44.292,15.621 49.379,15.621 P1.R1@49.445,15.555
NetC15_1: C15.1 C16.2 U2.28 | length 5.5
  Top Layer w0.229: v2(37.465,28.702) 37.665,28.502 U2.28@37.665,25.645
  Top Layer w0.508: v2(37.465,28.702) C15.1@37.465,30.096
  Bottom Layer w0.508: v2(37.465,28.702) C16.2@37.465,29.68
NetC17_2: C17.2 P1.R3 | length 6.5
  Top Layer w0.381: C17.2@43.053,17.945 43.203,18.095 P1.R3@49.445,18.095
NetLD1_1: LD1.1 R3.1 | length 2
  Top Layer w0.152: LD1.1@22.352,24.93 v1(22.352,25.908)
  Bottom Layer w0.152: R3.1@22.352,24.93 v1(22.352,25.908)
NetLD2_1: LD2.1 R5.2 | length 2
  Top Layer w0.152: LD2.1@20.955,24.93 v1(20.955,25.908)
  Bottom Layer w0.152: R5.2@20.955,24.93 v1(20.955,25.908)
NetLD3_1: LD3.1 R6.1 | length 2
  Top Layer w0.152: LD3.1@27.94,24.93 v1(27.94,25.908)
  Bottom Layer w0.152: R6.1@27.94,24.93 v1(27.94,25.908)
NetLD4_1: LD4.1 R8.1 | length 2
  Top Layer w0.152: LD4.1@26.543,24.93 v1(26.543,25.908)
  Bottom Layer w0.152: R8.1@26.543,24.93 v1(26.543,25.908)
NetLD5_1: LD5.1 R7.2 | length 2
  Top Layer w0.152: v1(2.032,29.845) LD5.1@3.01,29.845
  Bottom Layer w0.152: v1(2.032,29.845) R7.2@3.01,29.845
NetLD6_1: LD6.1 R10.1 | length 2
  Top Layer w0.152: LD6.1@25.146,24.93 v1(25.146,25.908)
  Bottom Layer w0.152: R10.1@25.146,24.93 v1(25.146,25.908)
NetLD7_1: LD7.1 R12.1 | length 2
  Top Layer w0.152: LD7.1@23.749,24.93 v1(23.749,25.908)
  Bottom Layer w0.152: R12.1@23.749,24.93 v1(23.749,25.908)
NetP1_L1: P1.L1 R22.2 | length 33
  Top Layer w0.152: R22.2@43.599,10.414 v1(44.577,10.414)
  Bottom Layer w0.152: v1(44.577,10.414) 46.228,10.414 46.863,9.779 58.674,9.779 59.309,10.414 59.309,14.478 60.325,15.494 60.325,22.479 59.175,23.629 P1.L1@59.175,26.325
NetP1_L3: P1.L3 R24.2 | length 21.9
  Top Layer w0.152: R24.2@43.599,11.811 v1(44.577,11.811)
  Bottom Layer w0.152: v1(44.577,11.811) 45.339,11.811 46.99,10.16 58.42,10.16 58.928,10.668 58.928,14.732 59.175,14.979 P1.L3@59.175,16.215
NetQ1_1: Q1.1 R1.1 | length 5.8
  Top Layer w0.152: Q1.1@16.38,23.175 17.084,23.175 17.424,22.835 17.424,20.498 18.58,19.342 R1.1@18.58,18.669
NetQ1_3: Q1.3 R3.2 | length 5.4
  Top Layer w0.152: Q1.3@19.18,22.225 19.18,21.587 19.431,21.336 21.463,21.336 v1(22.352,22.225)
  Bottom Layer w0.152: v1(22.352,22.225) R3.2@22.352,23.33
NetQ2_1: Q2.1 R4.1 | length 12.4
  Top Layer w0.152: Q2.1@16.38,26.985 17.465,26.985 18.085,26.365 18.085,20.777 19.431,19.431 19.431,17.399 19.177,17.145 R4.1@18.58,17.145
NetQ2_3: Q2.3 R5.1 | length 6.2
  Top Layer w0.152: Q2.3@19.18,26.035 19.812,26.035 20.091,25.756 20.091,22.708 20.574,22.225 v1(20.955,22.225)
  Bottom Layer w0.152: v1(20.955,22.225) R5.1@20.955,23.33
NetR9_2: R9.2 U1.32 | length 2.8
  Top Layer w0.152: v1(22.225,18.923) 22.733,18.923 23.035,18.621 U1.32@23.035,17.56
  Bottom Layer w0.152: R9.2@22.225,18.072 v1(22.225,18.923)
NetR21_2: R21.2 U2.25 | length 6
  Top Layer w0.152: U2.25@38.865,25.645 38.865,26.292 39.116,26.543 40.259,26.543 42.037,28.321 R21.2@42.037,29.68
NetR25_2: R25.2 U2.24 | length 2.9
  Top Layer w0.152: U2.24@39.615,24.895 40.287,24.895 41.453,26.06 41.974,26.06 R25.2@41.999,26.035
OUT_RTS: J4.9 U3.6 | length 18.2
  Top Layer w0.152: v1(1.143,17) J4.9@2.87,17 ; v1(14.589,15.875) U3.6@14.589,16.69
  Signal Layer 1 w0.152: v1(1.143,17) 5.276,17 7.925,14.351 13.97,14.351 14.589,14.97 v1(14.589,15.875)
OUT_TXD: J4.7 U3.3 | length 17.1
  Top Layer w0.152: v1(1.143,19) J4.7@2.87,19 ; U3.3@13.089,16.69 13.089,15.613 v1(13.208,15.494)
  Signal Layer 1 w0.152: v1(1.143,19) 4.241,19 8.255,14.986 12.954,14.986 13.208,15.24 v1(13.208,15.494)
PB_04: U1.24 U2.5 | length 12.9
  Top Layer w0.152: U1.24@26.235,17.56 26.235,19.072 27.28,20.117 32.537,20.117 33.985,21.565 33.985,22.555 34.725,23.295 U2.5@35.315,23.295
PB_05: LD7.2 R14.2 U1.25 U2.4 | length 22.9
  Top Layer w0.152: LD7.2@23.749,23.33 24.511,22.568 24.511,20.066 v1(25.654,18.923) 25.835,18.742 U1.25@25.835,17.56 ; v1(34.163,23.495) 34.363,23.695 U2.4@35.315,23.695
  Bottom Layer w0.152: R14.2@23.622,18.072 25.311,18.072 25.654,18.415 v1(25.654,18.923) 25.654,19.812 26.035,20.193 33.35,20.193 34.163,21.006 v1(34.163,23.495)
PB_06: U1.16 U2.15 | length 12
  Top Layer w0.152: U1.16@30.26,16.335 31.067,16.335 31.75,17.018 v1(32.004,17.018) ; U2.15@38.465,21.345 38.465,20.463 v1(38.735,20.193)
  Bottom Layer w0.152: v1(32.004,17.018) 33.172,17.018 33.378,17.224 36.883,17.224 38.735,19.075 v1(38.735,20.193)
